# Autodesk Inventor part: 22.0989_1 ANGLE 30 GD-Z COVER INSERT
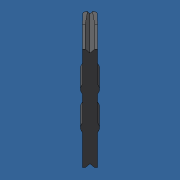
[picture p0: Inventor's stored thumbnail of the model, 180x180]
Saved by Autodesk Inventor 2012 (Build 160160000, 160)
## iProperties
Created: 2017-01
Part Number: 22.0989_1 ANGLE 30 GD-Z COVER INSERT
Material: ABS Plastic
Document SubType Name: Modeling
Designer: Admin
Density: 1.06 g/cm^3
Mass: 0.415425 g
Surface Area: 5.18315 cm^2
Volume: 0.391911 cm^3
Author: Admin
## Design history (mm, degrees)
feature "Base1"
body "Solid1"
